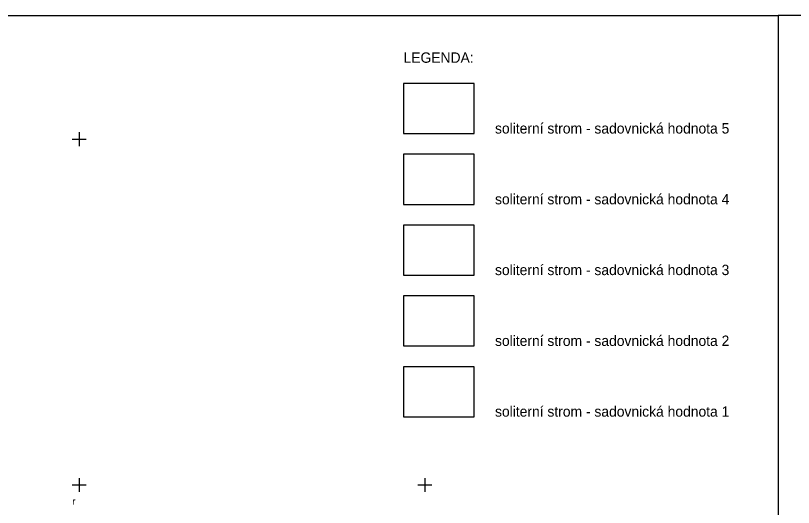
# Model space of a CAD drawing. Extents: x -740053 to -737517, y -1033516 to -1032476.
# Drawn here: x -739209.2 to -739096.7, y -1032553.3 to -1032482.1 of the extents above; entities that cross this region are included whole.
import ezdxf

# ---------------------------------------------------------------- set-up
doc = ezdxf.new("R2010")
doc.units = 0
for name, color, linetype in [('ctv-sit', 7, 'Continuous'), ('Predmety bez rozlišeni', 7, 'Continuous'), ('promika-formát', 7, 'Continuous'), ('Znacky-kultury', 7, 'Continuous')]:
    doc.layers.add(name, color=color, linetype=linetype)

# ---------------------------------------------------------------- blocks, each defined once
blk = doc.blocks.new('p_orna')
blk.add_text('r', height=2).set_placement((0, 0))
blk = doc.blocks.new('ctvsit')
for p, q in [((2, 0), (-2, 0)), ((0, -2), (0, 2))]:
    blk.add_line(p, q)

msp = doc.modelspace()

# ---------------------------------------------------------------- linework, layer by layer
at = {"layer": 'Predmety bez rozlišeni'}
for p, q in [((-739308.88, -1032482.13), (-739203.88, -1032482.13)), ((-739203.88, -1032482.13), (-739098.88, -1032482.13))]:
    msp.add_line(p, q, dxfattribs=at)
for points in [[(-739153.09, -1032499.19), (-739142.86, -1032499.19), (-739142.86, -1032491.96), (-739153.09, -1032491.96)], [(-739153.09, -1032509.43), (-739142.86, -1032509.43), (-739142.86, -1032502.19), (-739153.09, -1032502.19)], [(-739153.09, -1032519.66), (-739142.86, -1032519.66), (-739142.86, -1032512.43), (-739153.09, -1032512.43)], [(-739153.09, -1032529.9), (-739142.86, -1032529.9), (-739142.86, -1032522.66), (-739153.09, -1032522.66)], [(-739153.09, -1032540.13), (-739142.86, -1032540.13), (-739142.86, -1032532.9), (-739153.09, -1032532.9)]]:
    msp.add_lwpolyline(points, close=True, dxfattribs=at)
at = {"layer": 'promika-formát'}
msp.add_lwpolyline([(-739098.88, -1032630.63), (-738993.88, -1032630.63), (-738993.88, -1032482.13), (-739098.88, -1032482.13)], close=True, dxfattribs=at)

# ---------------------------------------------------------------- block references
at = {"layer": 'ctv-sit', "xscale": 0.5, "yscale": 0.5, "rotation": 180}
for p in [(-739200, -1032500), (-739200, -1032550), (-739150, -1032550)]:
    msp.add_blockref('ctvsit', p, dxfattribs=at)
at = {"layer": 'Znacky-kultury', "xscale": 0.5, "yscale": 0.5}
msp.add_blockref('p_orna', (-739201, -1032552.87), dxfattribs=at)

# ---------------------------------------------------------------- texts
at = {"layer": 'Predmety bez rozlišeni'}
for s, p in [('LEGENDA:', (-739153.09, -1032488.96)), ('soliterní strom - sadovnická hodnota 5', (-739139.86, -1032499.19)), ('soliterní strom - sadovnická hodnota 4', (-739139.86, -1032509.43)), ('soliterní strom - sadovnická hodnota 3', (-739139.86, -1032519.66)), ('soliterní strom - sadovnická hodnota 2 ', (-739139.86, -1032529.9)), ('soliterní strom - sadovnická hodnota 1', (-739139.86, -1032540.13))]:
    msp.add_text(s, height=1.5, dxfattribs=at).set_placement(p)

doc.saveas('drawing.dxf')
